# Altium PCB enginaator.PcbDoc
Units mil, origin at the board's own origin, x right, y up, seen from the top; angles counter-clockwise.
Board outline 5118.11 x 2283.46 mil, 2 copper layers (Top Layer, Bottom Layer); 70 components, 110 nets, 347 pads, 112 vias.
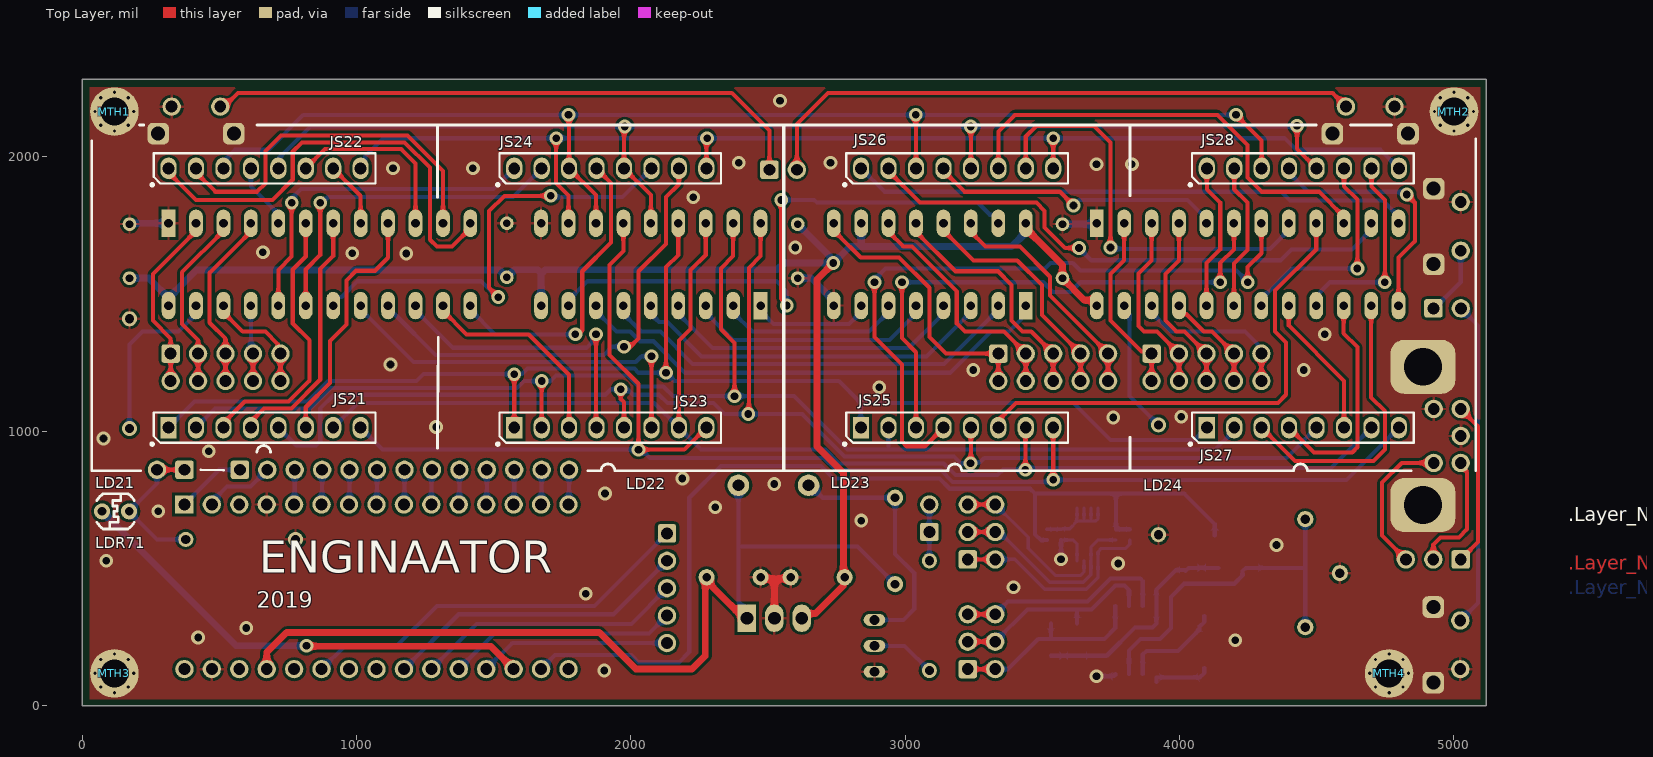
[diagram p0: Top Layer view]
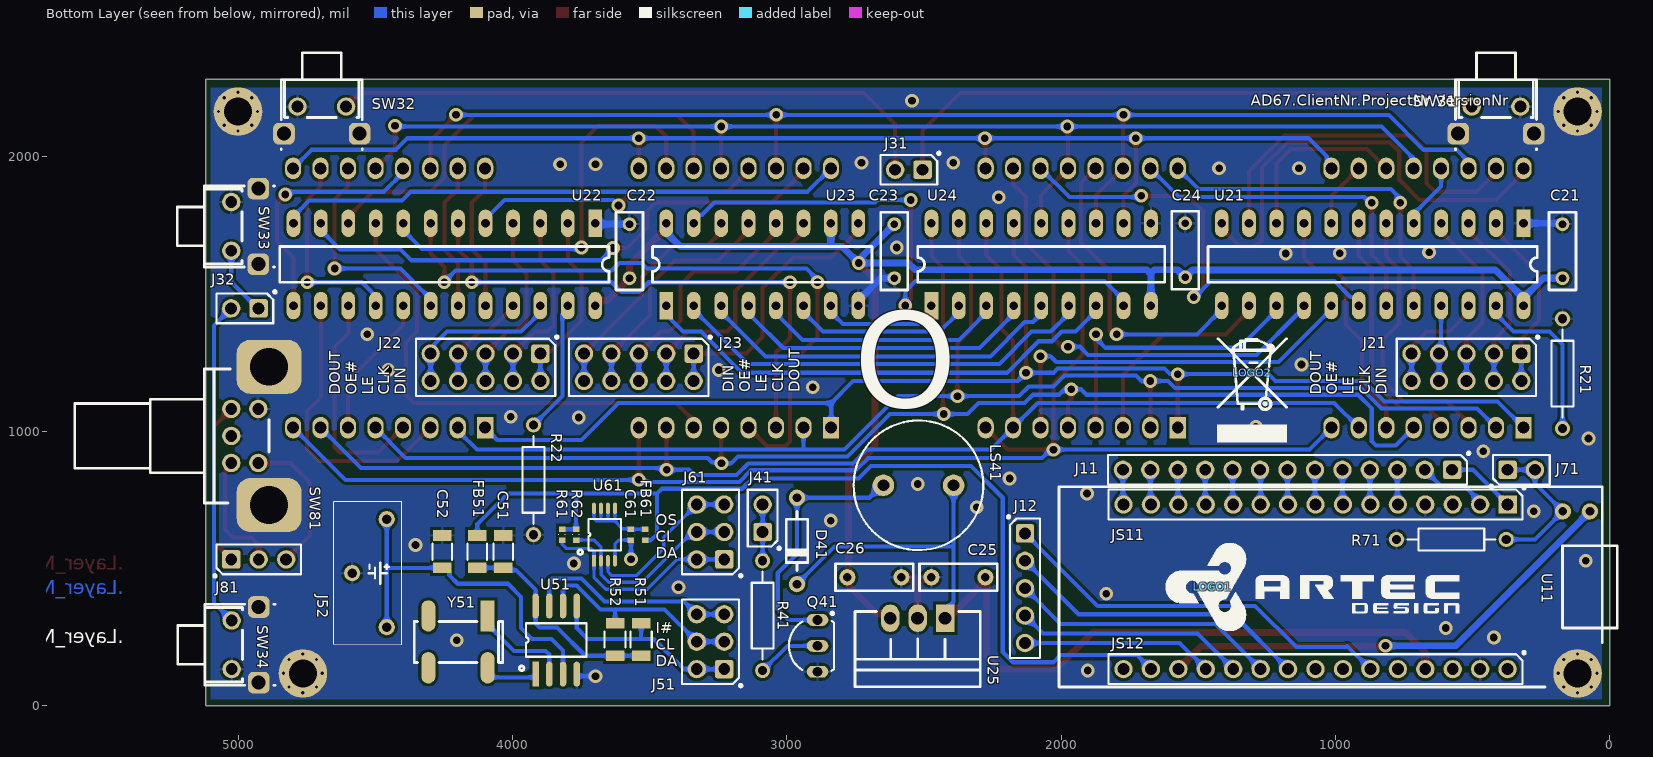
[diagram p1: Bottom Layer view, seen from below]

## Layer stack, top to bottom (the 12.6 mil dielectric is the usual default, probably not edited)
Top Solder: solder mask 0.4, Solder Resist, Dk 3.5
Top Layer: signal copper 1.4
Dielectric 1: dielectric 12.6, FR-4, Dk 4.8
Bottom Layer: signal copper 1.4
Bottom Solder: solder mask 0.4, Solder Resist, Dk 3.5

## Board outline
0,0 5118.11,0 5118.11,2283.46 0,2283.46

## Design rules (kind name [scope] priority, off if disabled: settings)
Clearance [All] p1: gap=10 ignorepadtopadclearanceinfootprint=FALSE except(0: Arc-Hole Track-Hole SMDPad-Hole THPad-Hole Via-Hole Fill-Hole Poly-Hole Region-Hole Text-Hole)
HoleSize [All] p1: absolutevalues=TRUE maxlimit=500 minlimit=10 maxpercent=80.000 minpercent=20.000
MinimumAnnularRing [All] p1: minimumring=3
MinimumSolderMaskSliver [All] p1: minsoldermaskwidth=3.94
PolygonConnect PolygonConnect_1 [InComponent('MTH*')] p1: connectstyle=Direct reliefconductorwidth=10 reliefentries=4 polygonreliefangle="90 Angle" airgapwidth=10
PolygonConnect [All] p2: connectstyle=Relief reliefconductorwidth=10 reliefentries=4 polygonreliefangle="90 Angle" airgapwidth=10
RoutingVias [All] p1: holewidth=28 width=50 viastyle="Through Hole" minholewidth=28 minwidth=50 maxholewidth=28 maxwidth=50
SilkToSilkClearance [All] p1: silktosilkclearance=6
SilkToSolderMaskClearance [IsPad] p1: minsilkscreentomaskgap=6 clearancetoexposedcopper=TRUE
SolderMaskExpansion [All] p1: expansion=3
Width [All] p1: maxlimit=25 minlimit=10 preferedwidth=10
26 further rules are at their usual default settings.

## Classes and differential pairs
net class ROW[1..8]: ROW1 ROW2 ROW3 ROW4 ROW5 ROW6 ROW7 ROW8
net class COL[1..32]: COL1 COL2 COL3 COL4 COL5 COL6 COL7 COL8 COL9 COL10 COL11 COL12 COL13 COL14 COL15 COL16 COL17 COL18 COL19 COL20 COL21 COL22 COL23 COL24 COL25 COL26 COL27 COL28 COL29 COL30 COL31 COL32

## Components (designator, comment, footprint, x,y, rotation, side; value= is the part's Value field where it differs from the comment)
C21 "100nF" CAP_TH_RADIAL_5MM#1 173.11,1755.31 r270 bottom value=100nF,radial,5mm
C22 "100nF" CAP_TH_RADIAL_5MM#1 3573.11,1755.31 r270 bottom value=100nF,radial,5mm
C23 "100nF" CAP_TH_RADIAL_5MM#1 2608.11,1558.46 r90 bottom value=100nF,radial,5mm
C24 "100nF" CAP_TH_RADIAL_5MM#1 1548.11,1758.46 r270 bottom value=100nF,radial,5mm
C25 "10uF" CAP_TH_RADIAL_5MM#2 2276.26,468.31 r0 bottom value=10uF,radial,5mm
C26 "22uF" CAP_TH_RADIAL_5MM#2 2779.45,468.31 r180 bottom value=22uF,radial,5mm
C51 "1206,100n,50V" C1206 4033.41,561.75 r90 bottom
C52 "1206,100n,50V" C1206 4255.33,561.75 r90 bottom
C61 "0402,C100n,16V" C0402 3568.11,623.46 r270 bottom
D41 "1N4001RLG" DIODE_TH_4X2MM 2963.11,758.11 r270 bottom
FB51 "1206,FB220,4A" L1206 4128.11,561.75 r270 bottom
FB61 "0402,FB120,1.2A" L0402 3516.22,623.46 r270 bottom
J11 "HDR1X13" HDRTHV254P_1X13 775.28,860.04 r0 bottom locked
J12 "HDR1X5" HDRTHV254P_1X5 2131.97,428.47 r270 bottom
J21 "HDR2X5" HDRTHv254P_2X5 523.11,1233.46 r0 bottom
J22 "HDR2X5" hdrthv254p_2x5 4098.11,1233.46 r0 bottom
J23 "HDR2X5" hdrthv254p_2x5 3539.45,1233.46 r0 bottom
J31 "HDR1X2" HDRTHV254P_1X2 2555.2,1953.46 r0 bottom
J32 "HDR1X2" HDRTHV254P_1X2 4975.11,1448.46 r0 bottom
J41 "HDR1X2" HDRTHV254P_1X2 3088.11,683.47 r90 bottom
J51 "HDR2X3" HDRTHV254P_2X3 3278.11,233.46 r90 bottom
J52 "S8401-46" S8401-46 4521.1,483.19 r90 bottom
J61 "HDR2X3" HDRTHV254P_2X3 3278.11,633.47 r90 bottom
J71 "HDR1X2" HDRTHV254P_1X2 323.11,860.04 r180 bottom
J81 "HDR1X3" HDRTHV254P_1X3 4924.68,533.46 r180 bottom
JS11 "SOCKET_1X15" HDRTHV254P_1X15_MECH 573.11,733.46 r0 bottom
JS12 "SOCKET_1X15" HDRTHV254P_1X15_MECH 573.11,133.46 r0 bottom
JS21 "SOCKET_1X8" HDRTHV254P_1X8_MECH 515.43,1013.78 r0 top
JS22 "SOCKET_1X8" HDRTHV254P_1X8_MECH 515.43,1958.66 r0 top
JS23 "SOCKET_1X8" HDRTHV254P_1X8_MECH 1775.28,1013.78 r0 top
JS24 "SOCKET_1X8" HDRTHV254P_1X8_MECH 1775.28,1958.66 r0 top
JS25 "SOCKET_1X8" HDRTHV254P_1X8_MECH 3039.45,1013.78 r0 top
JS26 "SOCKET_1X8" HDRTHV254P_1X8_MECH 3039.45,1958.66 r0 top
JS27 "SOCKET_1X8" HDRTHV254P_1X8_MECH 4299.29,1013.78 r0 top
JS28 "SOCKET_1X8" HDRTHV254P_1X8_MECH 4299.29,1958.66 r0 top
LD21 "KWM-30881AGB" LED8X8_32X32MM 665.43,1486.22 r90 top locked
LD22 "KWM-30881AGB" LED8X8_32X32MM 1925.28,1486.22 r90 top locked
LD23 "KWM-30881AGB" LED8X8_32X32MM 3189.45,1486.22 r90 top locked
LD24 "KWM-30881AGB" LED8X8_32X32MM 4449.29,1486.22 r90 top locked
LDR71 "NSL-5112" PHOTODIODE_4MM 171.54,708.46 r180 top
LOGO1 "LOGO_ARTEC" LOGO_ARTEC 1448.11,433.46 r180 bottom
LOGO2 "LOGO_RECBIN" LOGO_RECBIN 1303.11,1213.46 r180 bottom
LS41 "CCG-1206" BUZZER_12MM 2392.2,803.46 r0 bottom
MTH1 "MTHOLE2.6MM" MTHOLE2.6MM 118.11,2165.35 r0 top
MTH2 "MTHOLE2.6MM" MTHOLE2.6MM 5000,2165.35 r0 top
MTH3 "MTHOLE2.6MM" MTHOLE2.6MM 118.11,118.11 r0 top
MTH4 "MTHOLE2.6MM" MTHOLE2.6MM 4763.78,118.11 r0 top
Q41 "2N3904TAR" TO-226-AA-WIDE 2888.11,218.46 r180 bottom
R21 "1K8 1/4W" AXIAL-0.4 173.11,1210.43 r90 bottom
R22 "1K8 1/4W" AXIAL-0.4 3923.11,823.46 r270 bottom
R41 "180R 1/4W" AXIAL-0.4 3088.11,328.46 r270 bottom
R51 "1206,R10K" R1206 3530.8,241.34 r270 bottom
R52 "1206,R10K" R1206 3625.8,241.34 r270 bottom
R61 "0402,R10K" R0402 3818.58,623.46 r90 bottom
R62 "0402,R10K" R0402 3768.11,623.46 r90 bottom
R71 "10K 1/4W" AXIAL-0.4 578.11,606.46 r180 bottom
SW31 "EVQ-PF106K" SW_6X6_RA 326.78,2183.46 r0 bottom
SW32 "EVQ-PF106K" SW_6X6_RA 4606.25,2183.46 r0 bottom
SW33 "EVQ-PF106K" SW_6X6_RA 5024.69,1835.63 r270 bottom
SW34 "EVQ-PF106K" SW_6X6_RA 5023.11,310.63 r270 bottom
SW81 "EN12-VS11AF18" ROT_ENC_RA_12X12 5024.69,1081.89 r0 bottom
U11 "NUCLEO-F031K6" NUCLEO32 373.11,733.46 r270 bottom locked
U21 "MAX6971ANG+" DIP24-NARROW 315.43,1758.46 r270 bottom locked
U22 "MAX6971ANG+" DIP24-NARROW 3698.11,1758.46 r270 bottom locked
U23 "SN74AHC595N" DIP16 3439.45,1458.46 r90 bottom locked
U24 "TBD62783APG" DIP18 2473.11,1458.46 r90 bottom locked
U25 "VXO7803-500" VXO7803-500 2523.11,318.98 r0 bottom
U51 "PCF85263AT/AJ" SO8_HANDSOLDER 3915.63,135.12 r90 bottom
U61 "LM75ADP,118" SOT505-1_HANDSOLDER 3702.95,538.31 r90 bottom
Y51 "ABS25-32.768KHZ-6-T" XTAL_8X3.8MM_HANDSOLDER 4090.13,307.51 r0 bottom

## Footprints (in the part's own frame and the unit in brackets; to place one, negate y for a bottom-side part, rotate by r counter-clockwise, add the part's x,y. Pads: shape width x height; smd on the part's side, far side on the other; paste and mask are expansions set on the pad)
AXIAL-0.4 [mm] "Axial Device, Thru-Hole; 2 Leads; 0.4 in Pin Spacing"
  round 1.4 hole 0.85: 1(-5.08,0) 2(5.08,0)
  silkscreen extent -4.06,-1.02 4.06,1.02
BUZZER_12MM [mm]
  round 2 hole 1.1: 1(0,0) 2(6.5,0)
  silkscreen extent -2.75,-6 9.25,6
C0402 [mm]
  rect 0.5x0.6 smd: 1(-0.5,0) 2(0.5,0)
  silkscreen extent -0.01,-0.3 0,0.3, body extent -0.5,-0.25 0.5,0.25, height 0.5
C1206 [mm]
  rect 1x1.7 smd: 1(-1.5,0) 2(1.5,0)
  silkscreen extent -0.75,-0.9 0.75,0.9, body extent -1.6,-0.8 1.6,0.8, height 1.6
CAP_TH_RADIAL_5MM#1 [mil]
  round 50 hole 28: 1(0,0) 2(196.85,0)
  silkscreen extent -43,-49 240,49
CAP_TH_RADIAL_5MM#2 [mil]
  round 59.06 hole 31.5: 1(0,0) 2(196.85,0)
  silkscreen extent -43,-49 240,49
DIODE_TH_4X2MM [mm]
  round 1.5 hole 0.8: 1(0,0) 2(8,0)
  silkscreen extent 1.27,-1 6.73,1
DIP16 [mm]
  rect 2.54x1.27 hole 0.8: 1(0,0)
  oval 2.54x1.27 hole 0.8: 2(0,-2.54) 3(0,-5.08) 4(0,-7.62) 5(0,-10.16) 6(0,-12.7) 7(0,-15.24) 8(0,-17.78) 9(7.62,-17.78) 10(7.62,-15.24) 11(7.62,-12.7) 12(7.62,-10.16) 13(7.62,-7.62) 14(7.62,-5.08) 15(7.62,-2.54) 16(7.62,0)
  silkscreen extent 2.16,-19.05 5.46,1.27
DIP18 [mm]
  rect 2.54x1.27 hole 0.8: 1(0,0)
  oval 2.54x1.27 hole 0.8: 2(0,-2.54) 3(0,-5.08) 4(0,-7.62) 5(0,-10.16) 6(0,-12.7) 7(0,-15.24) 8(0,-17.78) 9(0,-20.32) 10(7.62,-20.32) 11(7.62,-17.78) 12(7.62,-15.24) 13(7.62,-12.7) 14(7.62,-10.16) 15(7.62,-7.62) 16(7.62,-5.08) 17(7.62,-2.54) 18(7.62,0)
  silkscreen extent 2.16,-21.59 5.46,1.27
DIP24-NARROW [mm]
  rect 2.54x1.27 hole 0.8: 1(0,0)
  oval 2.54x1.27 hole 0.8: 2(0,-2.54) 3(0,-5.08) 4(0,-7.62) 5(0,-10.16) 6(0,-12.7) 7(0,-15.24) 8(0,-17.78) 9(0,-20.32) 10(0,-22.86) 11(0,-25.4) 12(0,-27.94) 13(7.62,-27.94) 14(7.62,-25.4) 15(7.62,-22.86) 16(7.62,-20.32) 17(7.62,-17.78) 18(7.62,-15.24) 19(7.62,-12.7) 20(7.62,-10.16) 21(7.62,-7.62) 22(7.62,-5.08) 23(7.62,-2.54) 24(7.62,0)
  silkscreen extent 2.16,-29.21 5.46,1.27
HDRTHV254P_1X2 [mm] "Header, vertical, through-hole, 2.54mm pitch, 1X2"
  rrect25% 1.7x1.7 hole 1.1: 1(-1.27,0)
  round 1.7 hole 1.1: 2(1.27,0)
  silkscreen extent -2.9,-1.65 2.63,1.38, body extent -2.54,-1.27 2.54,1.27, height 9.5
HDRTHV254P_1X3 [mm] "Header, vertical, through-hole, 2.54mm pitch, 1X3"
  rrect25% 1.7x1.7 hole 1.1: 1(-2.54,0)
  round 1.7 hole 1.1: 2(0,0) 3(2.54,0)
  silkscreen extent -4.18,-1.65 3.9,1.38, body extent -3.81,-1.27 3.81,1.27, height 9.5
HDRTHV254P_1X5 [mm] "Header, vertical, through-hole, 2.54mm pitch, 1X5"
  rrect25% 1.7x1.7 hole 1.1: 1(-5.08,0)
  round 1.7 hole 1.1: 2(-2.54,0) 3(0,0) 4(2.54,0) 5(5.08,0)
  silkscreen extent -6.72,-1.65 6.45,1.38, body extent -6.35,-1.27 6.35,1.27, height 9.5
HDRTHV254P_1X8_MECH [mil] "Header, vertical, through-hole, 2.54mm pitch, 1X5"
  silkscreen extent -265,-65 554,55
HDRTHV254P_1X13 [mm] "Header, vertical, through-hole, 2.54mm pitch, 1X5"
  rrect25% 1.7x1.7 hole 1.1: 1(-5.08,0)
  round 1.7 hole 1.1: 2(-2.54,0) 3(0,0) 4(2.54,0) 5(5.08,0) 6(7.62,0) 7(10.16,0) 8(12.7,0) 9(15.24,0) 10(17.78,0) 11(20.32,0) 12(22.86,0) 13(25.4,0)
  silkscreen extent -6.72,-1.65 26.77,1.38, body extent -6.35,-1.27 26.67,1.27, height 9.5
HDRTHV254P_1X15_MECH [mil] "Header, vertical, through-hole, 2.54mm pitch, 1X5"
  silkscreen extent -265,-65 1254,54
HDRTHV254P_2X3 [mm] "Header, vertical, through-hole, 2.54mm pitch, 2X5"
  rrect25% 1.7x1.7 hole 1.1: 1(-2.54,-1.27)
  round 1.7 hole 1.1: 2(-2.54,1.27) 3(0,-1.27) 4(0,1.27) 5(2.54,-1.27) 6(2.54,1.27)
  silkscreen extent -4.18,-2.92 3.91,2.65, body extent -3.81,-2.54 3.81,2.54, height 9.5
HDRTHv254P_2X5 [mm] "Header, vertical, through-hole, 2.54mm pitch, 2X5"
  rrect25% 1.7x1.7 hole 1.1: 1(-5.08,-1.27)
  round 1.7 hole 1.1: 2(-5.08,1.27) 3(-2.54,-1.27) 4(-2.54,1.27) 5(0,-1.27) 6(0,1.27) 7(2.54,-1.27) 8(2.54,1.27) 9(5.08,-1.27) 10(5.08,1.27)
  silkscreen extent -6.72,-2.92 6.45,2.65, body extent -6.35,-2.54 6.35,2.54, height 9.5
hdrthv254p_2x5 [mm] "Header, vertical, through-hole, 2.54mm pitch, 2X5"
  rrect25% 1.7x1.7 hole 1.1: 1(-5.08,-1.27)
  round 1.7 hole 1.1: 2(-5.08,1.27) 3(-2.54,-1.27) 4(-2.54,1.27) 5(0,-1.27) 6(0,1.27) 7(2.54,-1.27) 8(2.54,1.27) 9(5.08,-1.27) 10(5.08,1.27)
  silkscreen extent -6.72,-2.92 6.45,2.65, body extent -6.35,-2.54 6.35,2.54, height 9.5
L0402 [mm]
  rect 0.5x0.6 smd: 1(-0.5,0) 2(0.5,0)
  silkscreen extent -0.01,0.31 0,0.31, body extent -0.5,-0.25 0.5,0.25, height 0.5
L1206 [mm]
  rect 1x1.7 smd: 1(-1.5,0) 2(1.5,0)
  silkscreen extent -0.75,-0.9 0.75,0.9, body extent -1.6,-0.8 1.6,0.8, height 0.8
LED8X8_32X32MM [mm]
  rect 2x1.5 hole 1.1: 1(-12,8.89)
  oval 2x1.5 hole 1.1: 2(-12,6.35) 3(-12,3.81) 4(-12,1.27) 5(-12,-1.27) 6(-12,-3.81) 7(-12,-6.35) 8(-12,-8.89) 9(12,-8.89) 10(12,-6.35) 11(12,-3.81) 12(12,-1.27) 13(12,1.27) 14(12,3.81) 15(12,6.35) 16(12,8.89)
  silkscreen extent -16,-16 16,16
LOGO_ARTEC [mil]
  silkscreen extent -171,-161 900,159
LOGO_RECBIN [mil]
  silkscreen extent -129,-253 126,124
MTHOLE2.6MM [mm] "Mounting hole for fine M3"
  round 4.5 hole 2.6: 1(0,0)
NUCLEO32 [mm]
  rect 1.7x1.7 hole 1.1: 1(0,0)
  round 1.7 hole 1.1: 2(0,-2.54) 3(0,-5.08) 4(0,-7.62) 5(0,-10.16) 6(0,-12.7) 7(0,-15.24) 8(0,-17.78) 9(0,-20.32) 10(0,-22.86) 11(0,-25.4) 12(0,-27.94) 13(0,-30.48) 14(0,-33.02) 15(0,-35.56) 16(15.24,0) 17(15.24,-2.54) 18(15.24,-5.08) 19(15.24,-7.62) 20(15.24,-10.16) 21(15.24,-12.7) 22(15.24,-15.24) 23(15.24,-17.78) 24(15.24,-20.32) 25(15.24,-22.86) 26(15.24,-25.4) 27(15.24,-27.94) 28(15.24,-30.48) 29(15.24,-33.02) 30(15.24,-35.56)
  silkscreen extent -1.65,-41.53 16.89,10.16
PHOTODIODE_4MM [mm]
  round 1.5 hole 0.8: 1(0,0) 2(2.5,0)
  silkscreen extent -0.48,-1.64 2.98,1.64
R0402 [mm]
  rect 0.5x0.6 smd: 1(-0.5,0) 2(0.5,0)
  silkscreen extent -0.02,-0.3 0.02,0.3, body extent -0.57,-0.27 0.58,0.28, height 0.41
R1206 [mm]
  rect 1x1.7 smd: 1(-1.5,0) 2(1.5,0)
  silkscreen extent -0.75,-0.97 0.75,0.97, body extent -1.68,-0.87 1.67,0.86, height 0.85
ROT_ENC_RA_12X12 [mm]
  rrect50% 6x5 hole 3.5: 1(-3.5,8.9) 2(-3.5,-3.9)
  round 1.7 hole 1.1: A(0,0) B(0,5) C(0,2.5) D(-2.5,0) E(-2.5,5)
  silkscreen extent -3.5,-3.7 14.5,8.7
S8401-46 [mm] "https://cdn.harwin.com/pdfs/S8401.pdf"
  round 1.5 hole 0.9: 1(-5,-1.6) 1(5,-1.6) 2(0,1.6)
  silkscreen extent -6.62,-3 6.6,3.3, body extent -11.45,-3 11.45,3.3, height 16.94
SO8_HANDSOLDER [mm]
  rect 2.3x0.6 smd: 1(-0.5,0)
  oval 2.3x0.6 smd: 2(-0.5,-1.27) 3(-0.5,-2.54) 4(-0.5,-3.81) 5(5.8,-3.81) 6(5.8,-2.54) 7(5.8,-1.27) 8(5.8,0)
  silkscreen extent 1.1,-4.7 4.2,0.9
SOT505-1_HANDSOLDER [mm]
  rect 1.05x0.35 smd: 1(-0.25,0)
  oval 1.05x0.35 smd: 2(-0.25,-0.65) 3(-0.25,-1.3) 4(-0.25,-1.95) 5(4.6,-1.95) 6(4.6,-1.3) 7(4.6,-0.65) 8(4.6,0)
  silkscreen extent 0.7,-2.5 3.6,0.5
SW_6X6_RA [mm]
  rrect50% 2x2 hole 1.3: 1(-1.25,2.5) 2(5.75,2.5)
  round 1.7 hole 1.1: A(0,0) B(4.5,0)
  silkscreen extent -1.5,-5 6,4
TO-226-AA-WIDE [mm] "TO, Flat Index; 3 In-Line, Axial Leads; Body Dia. 4.8mm; Leads 0.55 x 0.51 mm (max)"
  oval 2x1.1 hole 0.9: 1(0,2.4) 2(0,0) 3(0,-2.4)
  silkscreen extent -2.65,-2.31 1.52,3.13, body extent -2.65,-2.66 1.52,2.66, height 5.33
VXO7803-500 [mm]
  rect 1.7x2.54 hole 1.2: 1(-2.54,0)
  oval 1.7x2.54 hole 1.2: 2(0,0) 3(2.54,0)
  silkscreen extent -5.8,-0.64 5.8,6.35
XTAL_8X3.8MM_HANDSOLDER [mm]
  rect 1.3x2.9 smd: 1(0,-0.5)
  oval 1.3x2.9 smd: 2(0,4.3) x2(5.5,-0.5) x3(5.5,4.3)
  silkscreen extent -1.4,0 6.8,3.8

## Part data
C21 C22 C23 C24: library part CAP_RADIAL_5MM, "CAP 0.1UF 10% 63VDC RADIAL 5.0mm", Manufacturer="AVX Corporation"
C25 C26: library part CAP_RADIAL_5MM, Manufacturer="TDK Corporation"
C51 C52: "1206, C100n, 50V, +/-10%", Manufacturer=Yageo
C61: "0402, C100n, 16V, +/-10%, X7R", Manufacturer=Murata
D41: library part Diode, "Default Diode", Manufacturer="ON Semiconductor"
FB51: "1206, FB220, 4A, 20mOhm, FBMH3216HM221NT", Manufacturer="Taiyo Yuden"
FB61: "0402, FB120,1200mA", Manufacturer=TDK
J11 J21: Manufacturer=CONNFLY
J52: "S8401-46 Battery Holder, Vertical, H=16.9mm,  20mm coin, CR2032, -40+105C, TH, Harwin", Manufacturer=Harwin
JS11 JS12: library part HDR1X15_MECH, Manufacturer=NINIGI
JS21 JS22 JS23 JS24 JS25 JS26 JS27 JS28: library part HDR1X8_MECH, Manufacturer=CONNFLY
LD21 LD22 LD23 LD24: library part LED_MATRIX_8x8, Manufacturer="LUCKY LIGHT"
LDR71: library part PHOTORES, Manufacturer="Advanced Photonix"
LOGO1 LOGO2: library part BOM_only
LS41: library part Buzzer, "Magnetic Transducer Buzzer", Manufacturer="CUI Inc."
MTH1 MTH2 MTH3 MTH4: "MTHOLE2.6MM, M2.5 Mounting hole 2.9mm, plated", Manufacturer=NA
Q41: library part NPN, "NPN Bipolar Transistor", Manufacturer="ON Semi"
R21 R22 R71: library part Res2, "RES 1.8K OHM 1/4W 5% AXIAL", Manufacturer=Yageo
R41: library part Res2, "Resistor", Manufacturer=Yageo
R51 R52: "1206, R10K, 1/4W, 1%", Manufacturer=Yageo
R61 R62: "0402, R10K, 1/16W, 1%, RC0402FR-0710KL, Yageo", Manufacturer=Yageo
SW31 SW32 SW33 SW34: Manufacturer="Panasonic Electronic Components"
SW81: library part ROT_ENC_SW, Manufacturer="TT Electronics/BI"
U11: library part NUCLEO32, Manufacturer=STMicroelectronics
U21 U22: library part MAX6971, Manufacturer=Maxim
U23: library part 74HCT595, Manufacturer=TI
U24: library part TBD62xxx, Manufacturer="Toshiba Semiconductor and Storage"
U25: library part VXO78-500, Manufacturer="CUI Inc."
U51: library part PCF85263AT, Manufacturer=NXP
U61: library part LM75A, "SENSOR DIGITAL -55C-125C 8TSSOP", Manufacturer=NXP
Y51: library part XTAL, "Crystal Oscillator", Manufacturer=Abracon

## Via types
v1: diameter 50, hole 28, Top Layer to Bottom Layer, 80 vias
v2: diameter 23.62, hole 11.81, Top Layer to Bottom Layer, 32 vias

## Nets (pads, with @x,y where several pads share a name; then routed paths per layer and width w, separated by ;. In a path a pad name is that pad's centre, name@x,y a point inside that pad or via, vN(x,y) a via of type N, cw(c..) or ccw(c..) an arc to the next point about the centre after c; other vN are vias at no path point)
3V3: FB51.1 FB61.2 R61.2 R62.2 U11.29 | length 3621.9
  Bottom Layer w15: U11.29 1724.07,184.43 2002.15,184.43 2028.11,158.46 2175.19,158.46 2213.11,196.38 2213.11,758.11 2328.47,873.46 2693.11,873.46 2738.11,828.46 3124.9,828.46 3162.4,790.96 3455.61,790.96 3473.11,773.46 ; FB61.2 3494.81,603.78 3473.74,624.85 3473.74,772.84 3473.11,773.46 ; R61.2 R62.2 3768.11,773.46 ; FB51.1 4128.11,662.31 4016.95,773.46 3768.11,773.46 ; 3473.11,773.46 3768.11,773.46
3V3_LED: C21.2 C22.2 C23.2 C24.2 C26.1 U21.24 U22.24 U23.10 U23.16 U24.9 U25.3 | length 5774.9
  Top Layer w25: U25.3 2640.38,336.24 2672.74,336.24 2774.96,438.46 2774.96,847.95 2678.11,944.8 2678.11,1553.46 v1(2738.11,1613.46) ; U23.16 3439.45,1740.23 3573.11,1606.57 C22.2 3653.92,1477.66 3686.56,1477.66 3698.11,1466.11 U22.24
  Bottom Layer w25: C21.2 243.11,1558.46 303.88,1497.69 303.88,1488.25 U21.24@315.43,1476.7 ; U21.24 U21.24@315.43,1476.7 ; U24.9 1673.11,1543.46 ; 1673.11,1548.46 1673.11,1572.91 1674.5,1574.3 ; C23.2@2608.11,1748.55 C23.2 2725.61,1637.81 2725.61,1632.73 2738.11,1620.23 v1(2738.11,1613.46) ; U23.10@2834.66,1753.68 U23.10 2839.45,1677.13 2843.11,1673.46 ; U23.16 3439.45,1726.7 3426.95,1714.2 3426.95,1712.3 3388.11,1673.46 2843.11,1673.46 ; U21.24@315.43,1476.7 315.43,1485.79 418.11,1588.46 1521.26,1588.46 C24.2 1575.53,1589.04 1659.75,1589.04 1674.5,1574.3 ; 1674.5,1574.3 1689.24,1589.04 2533.11,1589.04 2557.54,1613.46 v1(2738.11,1613.46) ; v1(2738.11,1613.46) 2798.11,1673.46 2843.11,1673.46
3V3A: LDR71.2 U11.28 | length 1738.2
  Top Layer w25: v1(818.11,218.46) 819.45,217.12 1489.45,217.12 U11.28
  Bottom Layer w25: LDR71.2 563.11,218.46 v1(818.11,218.46)
BUZZER: J41.1 J41.2 R41.1 | length 205
  Bottom Layer w15: R41.1 J41.1 J41.2
COL1: LD21.13 U21.5 | length 241.6
  Bottom Layer w15: LD21.13 615.43,1892.14 715.43,1792.14 U21.5
COL2: LD21.3 U21.6 | length 1013.3
  Top Layer w15: LD21.3 515.43,1030.79 593.11,1108.46 753.11,1108.46 829.27,1184.62 829.27,1332.3 768.11,1393.46 768.11,1590.25 815.43,1637.57 U21.6
COL3: LD21.4 U21.7 | length 927.7
  Top Layer w15: LD21.4 615.43,1035.79 663.11,1083.46 763.47,1083.46 868.11,1188.11 868.11,1591.26 915.43,1638.58 U21.7
COL4: LD21.10 U21.8 | length 279.4
  Top Layer w15: LD21.10 1015.43,1858.66 U21.8
  Bottom Layer w15: U21.8@999.26,1789.55 1015.43,1773.38 U21.8
COL5: LD21.6 U21.9 | length 909.4
  Top Layer w15: LD21.6 815.43,1087.82 904.11,1176.5 904.11,1329.46 963.93,1389.28 963.93,1550.2 999.08,1585.35 1068.11,1585.35 1115.43,1632.68 U21.9
COL6: LD21.11 U21.10 | length 668.3
  Top Layer w15: LD21.11 885.24,2028.46 1163.25,2028.46 1215.43,1976.29 U21.10
COL7: LD21.15 U21.11 | length 1342.3
  Top Layer w15: LD21.15 415.43,1943.74 485.71,1873.46 638.11,1873.46 668.11,1903.46 668.11,2021.27 725.3,2078.46 1186.24,2078.46 1315.43,1949.27 U21.11
COL8: LD21.16 U21.12 | length 1660.2
  Top Layer w15: LD21.16 315.43,1943.74 415.71,1843.46 694.28,1843.46 767.96,1917.15 767.96,2019.32 802.11,2053.46 1175.88,2053.46 1268.11,1961.23 1268.11,1698.46 1293.11,1673.46 1348.11,1673.46 1415.43,1740.79 U21.12
COL9: LD22.13 U21.13 | length 1121.7
  Top Layer w15: v1(1798.11,1353.46) 1808.11,1353.46 1823.11,1368.46 1823.11,1583.46 1928.11,1688.46 1928.11,1905.83 LD22.13
  Bottom Layer w15: U21.13 1415.43,1443.54 1505.51,1353.46 v1(1798.11,1353.46)
COL10: LD22.3 U21.14 | length 767.7
  Top Layer w15: U21.14 1315.43,1439.96 1401.93,1353.46 1628.11,1353.46 1775.28,1206.3 LD22.3
COL11: LD22.4 U21.15 | length 1105.4
  Top Layer w15: v1(1873.11,1353.46) 1873.11,1025.95 1878.11,1020.95 1873.11,1015.95 LD22.4
  Bottom Layer w15: U21.15 1215.43,1441.08 1351.94,1304.57 1839.22,1304.57 1873.11,1338.46 v1(1873.11,1353.46)
COL12: LD22.10 U21.16 | length 1721.6
  Top Layer w15: U21.16@1115.43,1443.54 U21.16 ; v1(1975.28,1308.46) 1980.48,1303.26 1992.91,1303.26 2028.11,1338.46 2028.11,1583.46 2128.11,1683.46 2128.11,1853.46 2175.28,1900.63 LD22.10
  Bottom Layer w15: U21.16 1115.43,1442.94 1131.6,1426.77 1139.81,1426.77 1288.11,1278.46 1902,1278.46 1932,1308.46 v1(1975.28,1308.46)
COL13: LD22.6 U21.17 | length 1421.8
  Top Layer w15: LD22.6 v1(2075.28,1273.46)
  Bottom Layer w15: U21.17 1015.43,1442.94 1037.15,1421.22 1040.36,1421.22 1208.11,1253.46 2018.11,1253.46 2038.11,1273.46 v1(2075.28,1273.46)
COL14: LD22.11 U21.18 | length 1659.6
  Top Layer w15: v1(1517.21,1489.33) 1483.11,1523.43 1483.11,1802.46 1539.12,1858.46 v1(1708.11,1858.46)
  Bottom Layer w15: U21.18 915.43,1473.38 931.6,1489.55 946.52,1489.55 1004.22,1547.25 1454.32,1547.25 1512.25,1489.33 v1(1517.21,1489.33) ; v1(1708.11,1858.46) 1713.11,1853.46 1970.08,1853.46 LD22.11
COL15: LD22.15 U21.19 | length 1255.8
  Top Layer w15: U21.19 815.43,1589.73 868.11,1642.41 v1(868.11,1833.46)
  Bottom Layer w15: v1(868.11,1833.46) 875.28,1833.46 895.28,1853.46 1570.08,1853.46 LD22.15
COL16: LD22.16 U21.20 | length 1267.6
  Top Layer w15: U21.20 715.43,1588.31 763.93,1636.81 v1(763.93,1832.97)
  Bottom Layer w15: v1(763.93,1832.97) 763.93,1849.28 798.11,1883.46 1500.08,1883.46 LD22.16
COL17: LD23.13 U22.5 | length 1072.4
  Top Layer w15: LD23.13 3139.45,1949.86 3215.85,1873.46 3563.27,1873.46 v1(3613.27,1823.46)
  Bottom Layer w15: v1(3613.27,1823.46) 3633.27,1843.46 4028.11,1843.46 4074.52,1797.05 4075.05,1797.05 4098.11,1773.99 U22.5
COL18: LD23.3 U22.6 | length 1975.7
  Top Layer w15: v1(2988.11,1543.46) 2988.11,1339.8 3039.45,1288.46 LD23.3 ; v1(4148.11,1543.46) 4148.11,1613.46 4198.11,1663.47 U22.6
  Bottom Layer w15: v1(2988.11,1543.46) 3503.11,1543.46 3538.11,1508.46 3603.11,1508.46 3638.11,1543.46 v1(4148.11,1543.46)
COL19: LD23.4 U22.7 | length 2470.3
  Top Layer w15: v1(2888.11,1543.46) 2888.11,1343.46 2988.11,1243.46 2988.11,963.46 3005.76,945.81 3071.48,945.81 LD23.4 ; v1(4248.11,1543.46) 4248.11,1599.25 4298.11,1649.25 U22.7
  Bottom Layer w15: v1(2888.11,1543.46) 2888.11,1553.46 2928.11,1593.46 3510.03,1593.46 3530.03,1613.46 3610.61,1613.46 3638.11,1585.96 4208.11,1585.96 4235.77,1558.3 4235.77,1555.27 4248.11,1542.94 v1(4248.11,1543.46)
COL20: LD23.10 U22.8 | length 1554.8
  Top Layer w15: LD23.10 3439.45,2074.8 3478.11,2113.46 3688.11,2113.46 3748.11,2053.46 v1(3748.11,1669.88)
  Bottom Layer w15: v1(3748.11,1669.88) 3753.19,1664.8 4329.45,1664.8 4381.94,1717.3 4381.94,1727.38 4398.11,1743.54 U22.8
COL21: LD23.6 U22.9 | length 1817
  Top Layer w15: LD23.6 3339.45,1039.44 3403.48,1103.46 4358.11,1103.46 4388.11,1133.46 4388.11,1323.46 4348.11,1363.46 4348.11,1513.46 4498.11,1663.47 U22.9
COL22: LD23.11 U22.10 | length 1666.1
  Top Layer w15: LD23.11 3339.45,2093.46 3399.45,2153.46 4138.11,2153.46 4248.11,2043.46 4248.11,1924.74 4299.38,1873.46 4508.11,1873.46 4598.11,1783.46 U22.10
COL23: LD23.15 U22.11 | length 2009.5
  Top Layer w15: LD23.15 2939.45,1947.99 3053.98,1833.46 3478.11,1833.46 3508.11,1803.46 3508.11,1743.46 3583.27,1668.31 v1(3633.27,1668.31)
  Bottom Layer w15: v1(3633.27,1668.31) 3678.11,1623.46 4368.11,1623.46 4408.11,1663.47 4628.11,1663.47 4695.77,1731.13 4695.77,1756.13 U22.11
COL24: LD23.16 U22.12 | length 2056.2
  Bottom Layer w15: LD23.16 2924.65,1873.46 4370.28,1873.46 4402.78,1840.96 4740.61,1840.96 4781.94,1799.63 4781.94,1789.55 4798.11,1773.38 U22.12
COL25: LD24.13 U22.13 | length 920.1
  Top Layer w15: U22.13 4798.11,1633.04 4858.11,1693.04 4858.11,1833.46 v1(4828.11,1863.46)
  Bottom Layer w15: LD24.13 4399.29,1942.28 4468.11,1873.46 4818.11,1873.46 v1(4828.11,1863.46)
COL26: LD24.3 U22.14 | length 1062.4
  Top Layer w15: LD24.3 4421.34,891.73 4706.38,891.73 4748.11,933.46 4748.11,1073.46 4698.11,1123.46 U22.14
COL27: LD24.4 U22.15 | length 830.9
  Top Layer w15: LD24.4 4489.61,923.46 4629.32,923.46 4648.11,942.25 4648.11,1307.48 4598.11,1357.48 U22.15
COL28: LD24.10 U22.16 | length 741.1
  Top Layer w15: LD24.10 4699.29,1892.15 4748.11,1843.33 v1(4748.11,1543.46)
  Bottom Layer w15: U22.16 4498.11,1492.94 4511.7,1506.52 4511.7,1507.05 4548.11,1543.46 v1(4748.11,1543.46)
COL29: LD24.6 U22.17 | length 528
  Top Layer w15: U22.17 4398.11,1385.43 4599.29,1184.25 LD24.6
COL30: LD24.11 U22.18 | length 806
  Top Layer w15: LD24.11 4599.29,1893.16 4648.11,1844.34 v1(4648.11,1593.46)
  Bottom Layer w15: U22.18 4298.11,1473.99 4314.28,1490.16 4314.28,1499.63 4408.11,1593.46 v1(4648.11,1593.46)
COL31: LD24.15 U22.19 | length 541.1
  Top Layer w15: U22.19 4198.11,1611.2 4248.11,1661.2 4248.11,1833.46 4199.29,1882.28 LD24.15
COL32: LD24.16 U22.20 | length 541.1
  Top Layer w15: U22.20 4098.11,1613.47 4148.11,1663.46 4148.11,1833.46 4099.29,1882.28 LD24.16
D_CLK_C1: J21.3 J21.4 U21.3 | length 761.6
  Top Layer w15: J21.4 J21.3 423.11,1332.92 364.75,1391.28 364.75,1580.1 515.43,1730.79 U21.3
  Bottom Layer w15: J21.4 J21.3
D_CLK_C2: J22.3 J22.4 U22.3 | length 783.1
  Top Layer w15: U22.3 3898.11,1623.14 3850.93,1575.97 3850.93,1383.46 3870.93,1363.46 3918.11,1363.46 J22.3 J22.4
  Bottom Layer w15: J22.4 J22.3
D_CLK_R: J23.3 J23.4 U23.11 | length 983.3
  Top Layer w15: U23.11 2939.45,1727.13 2993.11,1673.46 3024.45,1673.46 3188.11,1509.8 3188.11,1393.46 3218.11,1363.46 3359.45,1363.46 J23.3 J23.4
  Bottom Layer w15: J23.4 J23.3
D_DIN_C1: J21.1 J21.2 U21.2 | length 767.1
  Top Layer w15: J21.2 J21.1 323.11,1338.47 258.11,1403.46 258.11,1573.46 415.43,1730.79 U21.2
  Bottom Layer w15: J21.2 J21.1
D_DIN_C2: J22.1 J22.2 U22.2 | length 775.4
  Top Layer w15: U22.2 3798.11,1623.47 3748.11,1573.46 3748.11,1403.46 3860.93,1290.64 3890.93,1290.64 J22.1 J22.2
  Bottom Layer w15: J22.2 J22.1
D_DIN_R: J23.9 J23.10 U23.14 | length 955.3
  Top Layer w15: U23.14 3239.45,1727.13 3293.11,1673.46 3418.11,1673.46 3528.11,1563.46 3528.11,1494.8 J23.9 J23.10
  Bottom Layer w15: J23.10 J23.9
D_DOUT_C1: J21.9 J21.10 U21.22 | length 509.3
  Top Layer w15: U21.22 515.43,1443.54 531.6,1427.38 531.6,1417.54 585.67,1363.46 668.11,1363.46 713.17,1318.4 713.17,1293.4 J21.9 J21.10
  Bottom Layer w15: J21.10 J21.9
D_DOUT_C2: J22.9 J22.10 U22.22 | length 698.8
  Top Layer w15: J22.10 J22.9
  Bottom Layer w15: U22.22 3898.11,1443.54 3914.28,1427.38 3914.28,1417.3 3968.11,1363.46 4238.11,1363.46 4283.54,1318.04 4283.54,1312.09 4298.11,1297.52 J22.9 J22.10
D_DOUT_R: J23.1 J23.2 U23.9 | length 1117.6
  Top Layer w15: U23.9 2739.45,1743.54 2755.62,1727.38 2755.62,1715.96 2838.11,1633.46 2978.11,1633.46 3088.11,1523.46 3088.11,1343.46 3148.11,1283.46 J23.1 J23.2
  Bottom Layer w15: J23.2 J23.1
D_LE_C1: J21.5 J21.6 U21.4 | length 761.3
  Top Layer w15: J21.6 J21.5 523.11,1337.73 465.04,1395.81 465.04,1577.91 608.74,1721.6 608.74,1751.77 U21.4
  Bottom Layer w15: J21.6 J21.5
D_LE_C2: J22.5 J22.6 U22.4 | length 775.4
  Top Layer w15: U22.4 3998.11,1623.47 3948.11,1573.47 3948.11,1403.46 3988.11,1363.46 4018.11,1363.46 J22.5 J22.6
  Bottom Layer w15: J22.6 J22.5
D_LE_R: J23.5 J23.6 U23.12 | length 991.3
  Top Layer w15: U23.12 3039.45,1727.13 3183.11,1583.46 3338.11,1583.46 3388.11,1533.46 3388.11,1403.46 3428.11,1363.46 3459.45,1363.46 J23.5 J23.6
  Bottom Layer w15: J23.6 J23.5
D_OE#_C1: J21.7 J21.8 U21.21 | length 378.2
  Top Layer w15: J21.8 J21.7
  Bottom Layer w15: U21.21 615.43,1291.14 J21.7 J21.8
D_OE#_C2: J22.7 J22.8 U22.21 | length 481.6
  Top Layer w15: U22.21 3998.11,1442.94 4014.28,1426.77 4024.81,1426.77 4088.11,1363.46 4118.11,1363.46 J22.7 J22.8
  Bottom Layer w15: J22.8 J22.7
D_OE#_R: J23.7 J23.8 U23.13 | length 975.8
  Top Layer w15: U23.13 3139.45,1732.13 3248.43,1623.14 3408.43,1623.14 3498.11,1533.46 3498.11,1424.8 J23.7 J23.8
  Bottom Layer w15: J23.8 J23.7
GND: C21.1 C22.1 C23.1 C24.1 C25.2 C26.2 C51.2 C52.2 C61.2 J52.2 MTH1.1 MTH2.1 MTH3.1 MTH4.1 Q41.3 R21.2 R22.2 R71.1 SW31.1 SW31.2 SW31.A SW32.1 SW32.2 SW32.B SW33.1 SW33.2 SW33.A SW34.1 SW34.2 SW34.B SW81.1 SW81.2 SW81.C SW81.D U11.4 U11.17 U21.1 U22.1 U23.8 U24.10 U25.2 U51.4 U61.4 | length 964.9
  Top Layer w25: C25.2@2463.99,463.08 2523.11,463.08 ; U25.2 2523.11,463.08 ; C26.2@2573.99,463.08 2523.11,463.08
  Bottom Layer w12: C61.2 3612.69,603.78 3626.18,590.28 U61.4
  Bottom Layer w15: v1(3568.11,533.47) C61.2 ; v1(3697.01,108.01) 3761.65,108.01 3765.63,112 U51.4
  Bottom Layer w25: C21.1 176.26,1758.46 U21.1 ; C23.1@2620.2,1558.46 2657.68,1558.46 2739.45,1476.7 U23.8 ; C22.1 3694.96,1755.31 U22.1
  other v1: 1903.11,128.46 4203.11,238.46 423.11,248.46 598.11,283.46 1835.41,408.46 3394.94,432.06 3776.01,518.46 88.11,528.46 4353.11,585.67 2839.45,674.8 278.11,708.46 2308.11,723.46 1905.85,773.46 2523.11,808.46 2188.11,828.46 461.75,927.33 78.11,973.84 1290.47,1015.95 3758.11,1050.25 4006.51,1053.46 2905.35,1161.08 3248.11,1223.46 4453.07,1223.46 1124.57,1243.81 4528.68,1353.46 984.42,1648.74 1181.33,1648.46 659.25,1652.33 2598.97,1669.88 2228.11,1853.46 1133.08,1958.46 1424.57,1958.66 3697.01,1973.46 3826.26,1973.46 2393.11,1978.61 2728.11,1978.51 2543.52,2205.24
  other v2: 118.11,47.24 4763.78,47.24 68,68 168.22,68 4713.67,68 4813.89,68 47.24,118.11 188.98,118.11 4692.91,118.11 4834.65,118.11 68,168.22 168.22,168.22 4713.67,168.22 4813.89,168.22 118.11,188.98 4763.78,188.98 118.11,2094.49 5000,2094.49 68,2115.24 168.22,2115.24 4949.89,2115.24 5050.11,2115.24 47.24,2165.35 188.98,2165.35 4929.13,2165.35 5070.87,2165.35 68,2215.46 168.22,2215.46 4949.89,2215.46 5050.11,2215.46 118.11,2236.22 5000,2236.22
NetC51_1: C51.1 FB51.2 R51.2 R52.2 U51.8 | length 833.7
  Bottom Layer w15: R51.2 R52.2 3734.61,182.29 3837.63,285.3 3901.3,285.3 3915.63,299.64 U51.8 3915.63,423.6 3986.58,494.55 4025.27,494.55 C51.1 C51.1@4034.33,502.69 ; C51.1@4022.15,490.51 C51.1@4034.33,502.69 ; FB51.2@4141.89,502.69 C51.1@4034.33,502.69
NetC52_1: C52.1 J52.1 U51.3 | length 1324
  Bottom Layer w15: U51.3 3815.63,201.08 3858.01,243.46 3928.11,243.46 3968.11,283.46 3968.11,396.48 4016.31,444.68 4199.32,444.68 4229.37,474.72 4229.37,490.51 4241.56,502.69 C52.1 4453.88,502.69 4458.11,498.46 ; J52.1@4458.11,286.34 4458.11,498.46 ; J52.1@4458.11,680.04 4458.11,498.46
NetC61_1: C61.1 FB61.1 U61.5 U61.6 U61.7 U61.8 | length 380.7
  Bottom Layer w12: FB61.1 C61.1 3570.08,643.15 3572.42,645.49 3600.14,645.49 3626.18,671.53 ; U61.5 3626.18,671.53 ; U61.6 3651.77,674.8 3653.11,673.46 ; U61.7 3677.36,674.21 3678.11,673.46 ; U61.8 3702.95,682.25 3694.17,673.46 3678.11,673.46 ; 3626.18,671.53 3628.11,673.46 3653.11,673.46 ; 3653.11,673.46 3678.11,673.46
NetD41_1: D41.1 LS41.2 Q41.1 | length 930.7
  Bottom Layer w15: LS41.2@2649.02,808.46 2699.37,758.11 D41.1 2963.11,553.46 3033.11,483.46 3033.11,352.95 2993.11,312.95 Q41.1
NetJ11_1: J11.1 U11.1 | length 266.8
  Bottom Layer w15: U11.1 373.11,754.37 394.02,754.37 499.68,860.04 J11.1
NetJ11_2: J11.2 U11.2 | length 260.5
  Bottom Layer w15: U11.2 473.11,743.46 528.11,798.46 613.7,798.46 J11.2
NetJ11_3: J11.3 U11.5 | length 127.5
  Bottom Layer w15: U11.5 775.28,735.63 J11.3
NetJ11_4: J11.4 U11.6 | length 127.5
  Bottom Layer w15: U11.6 875.28,735.63 J11.4
NetJ11_5: J11.5 U11.7 | length 127.5
  Bottom Layer w15: U11.7 975.27,735.63 J11.5
NetJ11_6: J11.6 U11.8 | length 127.5
  Bottom Layer w15: U11.8 1075.28,735.63 J11.6
NetJ11_7: J11.7 U11.9 | length 127.5
  Bottom Layer w15: U11.9 1175.28,735.63 J11.7
NetJ11_8: J11.8 U11.10 | length 127.5
  Bottom Layer w15: U11.10 1273.11,857.87 J11.8
NetJ11_9: J11.9 U11.11 | length 127.5
  Bottom Layer w15: U11.11 1375.28,735.63 J11.9
NetJ11_10: J11.10 U11.12 | length 127.5
  Bottom Layer w15: U11.12 1475.28,735.63 J11.10
NetJ11_11: J11.11 U11.13 | length 127.5
  Bottom Layer w15: U11.13 1575.28,735.63 J11.11
NetJ11_12: J11.12 U11.14 | length 127.5
  Bottom Layer w15: U11.14 1675.28,735.63 J11.12
NetJ11_13: J11.13 U11.15 | length 127.5
  Bottom Layer w15: U11.15 1775.28,735.63 J11.13
NetJ12_1: J12.1 U11.21 | length 1468
  Bottom Layer w15: U11.21 958.11,218.46 963.11,213.46 1143.11,213.46 1293.11,363.46 1866.97,363.46 J12.1
NetJ12_2: J12.2 U11.24 | length 1122.5
  Bottom Layer w15: U11.24 1373.11,333.46 1936.97,333.46 J12.2
NetJ12_3: J12.3 U11.25 | length 981.1
  Bottom Layer w15: U11.25 1438.11,298.46 2001.97,298.46 J12.3
NetJ12_4: J12.4 U11.26 | length 839.6
  Bottom Layer w15: U11.26 1503.11,263.46 2066.97,263.46 J12.4
NetJ12_5: J12.5 U11.27 | length 698.2
  Bottom Layer w15: U11.27 1568.11,228.47 J12.5
NetJ71_1: J71.1 J71.2 LDR71.1 R71.2 | length 642.5
  Top Layer w15: J71.2 J71.1
  Bottom Layer w15: J71.1 J71.2 273.11,810.04 LDR71.1 273.54,606.46 R71.2
NetJ81_1: J81.1 SW81.A | length 601
  Top Layer w15: J81.1 5088.11,596.89 5088.11,1018.47 SW81.A
NetJ81_2: J81.2 SW81.B | length 451.6
  Top Layer w15: J81.2 4924.69,587.01 4951.14,613.46 5018.11,613.46 5048.11,643.46 5048.11,850.29 5024.69,873.71 SW81.B
NetJ81_3: J81.3 SW81.E | length 533.7
  Top Layer w15: J81.3 4738.11,620.04 4738.11,813.46 4809.69,885.04 SW81.E
NetQ41_2: Q41.2 R41.2 | length 237.3
  Bottom Layer w15: Q41.2 2998.11,218.46 R41.2
NetR21_1: R21.1 U21.23 | length 625.2
  Bottom Layer w15: R21.1 173.11,1316.5 220.08,1363.46 351.1,1363.46 408.74,1421.1 408.74,1451.77 U21.23
NetR22_1: R22.1 U22.23 | length 486.8
  Bottom Layer w15: U22.23 3798.11,1443.46 3818.11,1423.46 3818.11,1128.46 R22.1
NetU51_1: U51.1 Y51.2 | length 216.9
  Bottom Layer w15: U51.1@3915.63,86.02 3915.63,103.47 4073.42,103.47 4090.13,120.18 Y51.2
NetU51_2: U51.2 Y51.1 | length 372
  Bottom Layer w15: U51.2 3865.63,186.48 3879.11,199.96 3993.9,199.96 4072.04,278.1 4072.04,287.9 4090.13,305.99 Y51.1
ROW1: LD21.9 LD22.9 LD23.9 LD24.9 U24.11 | length 4440.1
  Top Layer w15: v1(1728.11,2068.46) 1728.11,1904.84 1773.11,1859.84 U24.11 ; LD22.9 2275.28,2065.63 v1(2278.11,2068.46) ; LD23.9 v1(3539.45,2068.46)
  Bottom Layer w15: LD21.9 1015.43,1973.58 1031.6,1989.75 1031.6,2001.96 1098.11,2068.46 v1(1728.11,2068.46) v1(2278.11,2068.46) v1(3539.45,2068.46) 4383.11,2068.46 4425.41,2026.16 4731.79,2026.16 LD24.9
ROW1_P: U23.15 U24.8 | length 2139.1
  Top Layer w15: v1(2548.11,1843.46) 2548.11,1484.75 2568.11,1464.75 v1(2568.11,1458.46)
  Bottom Layer w15: U24.8 1773.11,1478.46 1841.9,1547.25 2531.02,1547.25 2568.11,1510.16 v1(2568.11,1458.46) ; v1(2548.11,1843.46) 2668.11,1843.46 2678.11,1833.46 3264.45,1833.46 3308.36,1789.55 3323.28,1789.55 3339.45,1773.38 U23.15
ROW2: LD21.14 LD22.14 LD23.14 LD24.14 U24.12 | length 4651.1
  Top Layer w15: v1(1773.11,2153.46) 1775.28,2151.3 LD22.14 1873.11,1860.83 U24.12 ; v1(3038.11,2153.46) 3039.45,2152.13 LD23.14 ; v1(4205.98,2153.46) 4299.29,2060.16 LD24.14
  Bottom Layer w15: LD21.14 515.43,1983.66 557.93,2026.16 678.89,2026.16 806.19,2153.46 v1(1773.11,2153.46) v1(3038.11,2153.46) v1(4205.98,2153.46)
ROW2_P: U23.1 U24.7 | length 1800.7
  Bottom Layer w15: U24.7 1873.11,1438.47 1948.11,1363.46 1998.11,1363.46 2033.11,1328.46 2083.11,1328.46 2198.11,1213.46 3163.11,1213.46 3313.11,1363.46 3378.11,1363.46 3421.95,1407.3 3421.95,1440.96 U23.1
ROW3: LD21.8 LD22.8 LD23.8 LD24.8 U24.13 | length 5312.1
  Top Layer w15: U24.13 1973.11,1656.72 1923.11,1606.72 1923.11,1278.46 2028.11,1173.46 v1(2028.11,933.46) 2194.96,933.46 LD22.8 ; v1(3539.45,823.46) LD23.8
  Bottom Layer w15: LD21.8 1095.75,933.46 v1(2028.11,933.46) 2040.69,933.46 2070.69,903.46 2703.11,903.46 2748.11,858.46 3130.25,858.46 3172.75,815.96 3539.45,815.96 v1(3539.45,823.46) 4608.98,823.46 LD24.8
ROW3_P: U23.2 U24.6 | length 1568.7
  Bottom Layer w15: U24.6 1973.11,1428.47 2038.11,1363.46 2108.11,1363.46 2225.61,1245.96 3141.87,1245.96 3339.45,1443.54 U23.2
ROW4: LD21.12 LD22.12 LD23.12 LD24.12 U24.14 | length 4528
  Top Layer w15: v1(1978.11,2110.96) 1975.28,2108.13 LD22.12 2073.11,1860.83 U24.14 ; LD23.12 v1(3239.45,2110.96) ; v1(4428.11,2113.46) 4428.11,2029.84 LD24.12
  Bottom Layer w15: LD21.12 715.43,1993.13 729.12,2006.82 729.12,2007.15 832.93,2110.96 v1(1978.11,2110.96) v1(3239.45,2110.96) 4425.61,2110.96 v1(4428.11,2113.46)
ROW4_P: U23.3 U24.5 | length 1351
  Bottom Layer w15: U24.5 2073.11,1428.47 2103.11,1398.46 2133.11,1398.46 2258.11,1273.46 3078.11,1273.46 3223.28,1418.63 3223.28,1427.38 3239.45,1443.54 U23.3
ROW5: LD21.1 LD22.1 LD23.1 LD24.1 U24.15 | length 4847.6
  Top Layer w15: LD22.1 v1(1575.28,1208.46) ; v1(2128.11,1213.46) 2128.11,1598.46 2173.11,1643.46 U24.15
  Bottom Layer w15: LD21.1 410.12,1108.46 822.4,1108.46 897.4,1183.46 1219.1,1183.46 1244.1,1208.46 1603.11,1208.46 1623.11,1228.46 2013.11,1228.46 2028.11,1213.46 v1(2128.11,1213.46) 2158.11,1183.46 2758.11,1183.46 2838.11,1103.46 ; LD23.1 2838.11,1015.12 2838.11,1103.46 ; LD24.1 4054.23,968.72 3747.86,968.72 3613.11,1103.46 2838.11,1103.46
ROW5_P: U23.4 U24.4 | length 1129.1
  Bottom Layer w15: U24.4 2173.11,1428.47 2298.11,1303.46 3013.11,1303.46 3123.28,1413.63 3123.28,1427.38 3139.45,1443.54 U23.4
ROW6: LD21.7 LD22.7 LD23.7 LD24.7 U24.16 | length 4940.8
  Top Layer w15: LD22.7 2175.28,1330.63 2218.11,1373.46 2218.11,1588.47 2273.11,1643.46 U24.16 ; v1(3438.11,860.04) 3438.11,1012.44 LD23.7
  Bottom Layer w15: LD21.7 1005.12,1103.46 2085.59,1103.46 LD22.7 2255.59,933.46 2709.45,933.46 2759.45,883.46 3140.61,883.46 3183.11,840.96 3336.95,840.96 3356.02,860.04 v1(3438.11,860.04) 3444.03,865.96 4551.48,865.96 LD24.7
ROW6_P: U23.5 U24.3 | length 901.3
  Bottom Layer w15: U24.3 2273.11,1443.54 2289.28,1427.38 2289.28,1417.3 2373.11,1333.46 2943.11,1333.46 3023.28,1413.63 3023.28,1427.38 3039.45,1443.54 U23.5
ROW7: LD21.2 LD22.2 LD23.2 LD24.2 U24.17 | length 4929.4
  Top Layer w15: LD22.2@1675.28,1018.11 v1(1675.28,1183.46) ; U24.17 2373.11,1638.46 2328.11,1593.46 2328.11,1372.28 2378.11,1322.28 v1(2378.11,1128.46)
  Bottom Layer w15: LD21.2 485.12,1083.46 832.75,1083.46 907.75,1158.46 1585.38,1158.46 1610.38,1183.46 v1(1675.28,1183.46) 1708.11,1183.46 1728.11,1203.46 1988.11,1203.46 2028.11,1163.46 2118.32,1163.46 2153.32,1128.46 v1(2378.11,1128.46) 2594.96,1128.46 2789.96,933.46 2938.11,933.46 ; LD23.2 2939.45,934.8 2938.11,933.46 ; LD24.2 4192.77,1007.26 4192.77,996.45 4129.79,933.46 2938.11,933.46
ROW7_P: U23.6 U24.2 | length 673.5
  Bottom Layer w15: U24.2 2373.11,1433.47 2443.11,1363.46 2868.11,1363.46 2923.28,1418.63 2923.28,1427.38 2939.45,1443.54 U23.6
ROW8: LD21.5 LD22.5 LD23.5 LD24.5 U24.18 | length 5130.7
  Top Layer w15: v1(1963.41,1153.46) 1963.41,1118.16 1975.28,1106.3 LD22.5 ; v1(2428.11,1063.15) 2428.11,1058.46 2430.61,1060.96 2430.61,1595.96 2473.11,1638.46 U24.18 ; v1(3238.11,883.46) 3239.45,884.8 LD23.5
  Bottom Layer w15: LD21.5 780.75,948.46 853.11,948.46 868.11,963.46 868.11,1083.46 918.11,1133.46 1908.11,1133.46 1928.11,1153.46 v1(1963.41,1153.46) 1988.11,1153.46 2008.11,1133.46 2103.11,1133.46 2133.11,1103.46 2301.32,1103.46 2341.63,1063.15 v1(2428.11,1063.15) 2624.76,1063.15 2779.45,908.46 3178.11,908.46 3203.11,883.46 v1(3238.11,883.46) 3241.7,887.05 3271.7,887.05 3288.11,903.46 4388.98,903.46 LD24.5
ROW8_P: U23.7 U24.1 | length 447.8
  Bottom Layer w15: U24.1 2473.11,1438.47 2520.61,1390.96 2795.61,1390.96 2823.28,1418.63 2823.28,1427.38 2839.45,1443.54 U23.7
RTC_INT#: J51.5 J51.6 U51.7 | length 886.2
  Top Layer w15: J51.5 J51.6
  Bottom Layer w15: J51.5 J51.6 3374,379.35 3664,379.35 3748.11,463.46 3856.84,463.46 3865.63,454.68 U51.7
RTC_SCL: J51.3 J51.4 R52.1 U51.6 | length 891.8
  Top Layer w15: J51.3 J51.4
  Bottom Layer w15: J51.3 J51.4 3445.9,351.26 3633.18,351.26 ; R52.1 3625.8,343.87 3633.18,351.26 ; U51.6 3815.63,422.16 3799.32,438.46 3765.71,438.46 3678.5,351.26 3633.18,351.26
RTC_SDA: J51.1 J51.2 R51.1 U51.5 | length 837.7
  Top Layer w15: J51.1 J51.2
  Bottom Layer w15: J51.1 J51.2 3374.89,133.46 3484.89,243.46 3528.11,243.46 ; R51.1 3530.8,246.15 3528.11,243.46 ; U51.5 3765.63,283.42 3725.68,243.46 3528.11,243.46
SW1: J31.1 SW31.B | length 2221.7
  Top Layer w15: SW31.B 518,2183.46 568,2233.46 2368.11,2233.46 2505.19,2096.38 J31.1
SW2: J31.2 SW32.A | length 2251.5
  Top Layer w15: J31.2 2605.2,2120.55 2718.11,2233.46 4558.07,2233.46 4608.07,2183.46 SW32.A@4622.13,2183.46
SW3: J32.1 SW33.B | length 253.1
  Bottom Layer w15: J32.1 4950.54,1473.89 4953.75,1473.89 5024.69,1544.83 SW33.B
SW4: J32.2 SW34.A | length 1190
  Bottom Layer w15: SW34.A 5087.11,374.63 5087.11,1386.46 J32.2
T_OS: J61.5 J61.6 U61.3 | length 700
  Top Layer w12: J61.5 J61.6
  Bottom Layer w12: J61.5 J61.6 3448.11,613.47 3448.11,573.46 3546.5,475.08 3639.01,475.08 3651.75,487.82 U61.3@3651.75,528.46
T_SCL: J61.3 J61.4 R62.1 U61.2 | length 838.4
  Top Layer w12: J61.3 J61.4
  Bottom Layer w12: J61.3 J61.4 3343.11,633.47 3526.49,450.08 3649.37,450.08 3676.75,477.46 U61.2@3676.75,528.46 ; U61.2 3677.36,578.81 3702.33,603.78 R62.1
T_SDA: J61.1 J61.2 R61.1 U61.1 | length 873.1
  Top Layer w12: J61.1 J61.2
  Bottom Layer w12: J61.1 3400.07,533.46 3508.46,425.08 3659.72,425.08 3702.95,468.31 U61.1 3702.95,561.75 3714.67,573.46 3803.58,573.46 3818.58,588.46 R61.1
USB5V: C25.1 D41.2 LS41.1 U11.19 U25.1 | length 3382
  Top Layer w25: U11.19 673.11,193.46 746.08,266.43 1885.14,266.43 2018.11,133.46 2223.11,133.46 2271.26,181.61 2271.26,463.31 C25.1 2276.26,455.1 2409.48,321.88 2414.84,327.25 2423.11,335.51 U25.1
  Bottom Layer w15: LS41.1@2392.2,808.46 2392.2,580.04 2392.2,379.37 U25.1@2418.11,353.46 ; 2393.11,580.04 2826.22,580.04 D41.2
pads on no net: U11.3 U11.16 U11.18 U11.20 U11.22 U11.23 U11.30 Y51.x2 Y51.x3

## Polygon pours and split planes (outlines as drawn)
GND on Top Layer "TOP_GND" (solid, pour order 0): 5094.96,2253.46 5094.96,24.61 28.11,24.61 28.11,2253.46
GND on Bottom Layer "BOT_GND" (solid, pour order 2): 5100.04,2252.27 5100.04,23.62 29.17,23.62 29.17,2252.27

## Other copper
Top Layer:
  text ".Layer_Name" at 5415.83,495.35 h50
Bottom Layer:
  region: 1698.11,1518.46
  region net 3V3_LED: 1673.11,1543.46 1673.11,1458.46
  region: 898.11,1958.46
  text ".Layer_Name" at 5415.83,406.47 h50

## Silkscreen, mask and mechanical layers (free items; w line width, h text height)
Top Overlay:
  lines w10: 209.13,2116.14 224.88,2116.14 ; 4622.52,2116.14 4772.13,2116.14
  text ".Layer_Name" at 5415.83,673.1 h50
  text "ENGINAATOR" at 645.11,446.33 h200
  text "2019" at 637.11,337.83 h100
Bottom Overlay:
  circle w10: c3966.54,136.81 r8.41
  circle w10: c3752.95,560.04 r8.41
  text "AD67.ClientNr.ProjectNr.VersionNr" at 1310.04,2186.02 h40
  text "DIN / OE# / LE / CLK / DOUT" at 2953.11,1143.46 h40 r270
  text "DOUT / OE# / LE / CLK / DIN" at 813.11,1133.11 h40 r270
  text "DOUT / OE# / LE / CLK / DIN" at 4388.11,1133.46 h40 r270
  text "O" at 2756.38,973.84 h600
  text "OS / CL / DA" at 3478.11,538.46 h40
  text ".Layer_Name" at 5415.83,228.73 h50
  text "I# / CL / DA" at 3478.11,143.46 h40
Top Solder:
  text ".Layer_Name" at 5415.83,584.22 h50
Bottom Solder:
  text ".Layer_Name" at 5415.83,300.94 h50
Mechanical 1 - Board Outline:
  the board outline again, w15
  text ".Layer_Name" at 5415.83,34.32 h50
Drill Drawing:
  drawing of 79 lines, arcs and shapes, not listed
  text "NOTES :    (UNLESS SPECIFIED OTHERWISE.)" at 7435.51,2721.13 h60
  text "1) MATERIAL : FR-4-2 NATURAL EPOXY/FIBERGLASS" at 7431.79,2594.94 h40
  text "53UM COPPER ON ALL LAYERS." at 7879.67,2488.43 h40
  text "2 SIDES PLATED." at 7880.67,2411.43 h40
  text "FINISHED THICKNESS:" at 7881.67,2325.43 h40
  text "10%" at 8828.23,2323.49 h50
  text "1,6mm" at 8489.47,2321.56 h50
  text "2) APPLY SOLDERMASK ON BOTH SIDES" at 7431.79,2140.93 h40
  text "COLOR : GREEN" at 7589.27,2015.93 h40
  text "FABRICATOR SHALL MAKE NECESSARY" at 7589.27,1890.93 h40
  text "MODIFICATIONS TO SOLDERMASK PHOTOPLOT FILES" at 7589.27,1765.93 h40
  text "FOR OPTIMAL SOLDERMASK COVERAGE BETWEEN" at 7589.27,1662.93 h40
  text "FINE PITCH COMPONENT LEADS." at 7589.27,1560.15 h40
  text "3) FINISH ALL EXPOSED COPPER SURFACES WITH" at 7431.79,1445.43 h40
  text "IMMERSION GOLD." at 7589.27,1320.43 h40
  text "4) HOLE SIZES APPLY AFTER PLATING." at 7431.79,1183.19 h40
  text "5) APPLY SILKSCREEN ON BOTH SIDES" at 7431.79,1067.47 h40
  text "COLOR : WHITE" at 7589.27,942.47 h40
  text "FABRICATOR SHALL MAKE NECESSARY" at 7589.27,817.47 h40
  text "MODIFICATIONS TO LEGEND PHOTOPLOT FILES" at 7589.27,692.47 h40
  text "TO ENSURE NO LEGEND INK COVERS ANY" at 7589.27,589.47 h40
  text "COMPONENT PAD OR VIA PAD." at 7589.27,486.69 h40
  text "6) MODIFIED PHOTOPLOT FILES ARE TO BE RETURNED" at 7431.79,384.47 h40
  text "BEFORE ORDER DELIVERED." at 7589.27,259.47 h40
  text "7) ALL PRINTED CIRCUIT BOARD NETS SHALL BE" at 7431.79,154.47 h40
  text ".Layer_Name" at 5415.83,139.85 h50
  text "ELECTRICALLY TESTED FOR OPENS AND SHORTS." at 7589.27,29.47 h40
  text "8) FABRICATION OF PCB TO COMPLY" at 7431.79,-78.53 h40
  text "WITH IPC-A-600  CLASS II , CURRENT REVISION." at 7589.25,-165.69 h40
  text "DRILLING DETAILS :" at 472.91,-236.55 h60
  text "STACKUP CONFIGURATION" at 1518.41,-1171.29 h50
  text "2 LAYER" at 2559.15,-1171.29 h50
  text "18+35um L1" at 804.17,-1395.99 h40
  text "SIGNALS+COMP." at 88.28,-1396.99 h40
  text "LAYER 1   (TOP SIDE)" at 1836.28,-1402.99 h40
  text "1,6mm" at 3850.35,-1467.46 h50
  text "10%" at 4194.83,-1467.46 h50
  text "~1460um" at 804.17,-1492.99 h40
  text "SIGNALS+COMP." at 102.95,-1590.29 h40
  text "18+35um L2" at 804.17,-1595.99 h40
  text "LAYER 2   (BOTTOM SIDE)" at 1836.28,-1602.99 h40
  text "Akadeemia tee 21/1, 3rd floor" at 8781.37,-2575.54 h50
  text "APPROVALS" at 6004,-2593.05 h55
  text "DATE" at 7079,-2593.05 h55
  text "Tallinn 12618, Estonia, EU" at 8781.33,-2699.02 h50
  text "DESIGNER:" at 5688.25,-2793.05 h45
  text ".PCBDesigner" at 6087.74,-2793.07 h50
  text ".Print_Date" at 6947.74,-2793.07 h50
  text "Tel: (+372) 671-8550" at 8781.38,-2815.54 h50
  text ".Print_Date" at 6947.74,-2993.03 h50
  text "CHECKER:" at 5688.25,-2993.05 h45
  text ".PCBChecker" at 6087.74,-2993.05 h50
  text "PRJ MGR:" at 5688.25,-3193.05 h45
  text ".ProjectManager" at 6087.74,-3193.05 h55
  text ".Print_Date" at 6947.74,-3193.05 h50
  text ".Schematic_Title / FABRICATION" at 7580.2,-3224.74 h100
  text "SIZE" at 7279,-3368.05 h45
  text "DRAWING NUMBER" at 7829,-3368.05 h45
  text "SCALE" at 8829,-3368.05 h45
  text "SHEET" at 9229,-3368.05 h45
  text "VERSION" at 9611.22,-3368.05 h45
  text "CLIENT:" at 5688.25,-3443.05 h45
  text "A4" at 7306,-3493.07 h55
  text "85.ClientNr.ProjectNr.VersionNr" at 7924,-3493.05 h50
  text "1 : 1" at 8854,-3493.05 h55
  text "1 OF 1" at 9210,-3493.07 h55
  text "01" at 9697.74,-3493.05 h55

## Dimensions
0,2283.46 to 0,0 on Bottom Overlay
0,2283.46 to 5118.11,2283.46 on Bottom Overlay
